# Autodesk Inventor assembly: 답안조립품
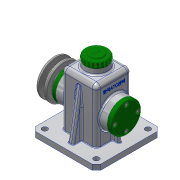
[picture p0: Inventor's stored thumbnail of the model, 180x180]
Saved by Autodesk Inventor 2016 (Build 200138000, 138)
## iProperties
Created: 2018-10
Part Number: 답안조립품
Material: 일반
Document SubType Name: Assembly
Designer: user
Author: user
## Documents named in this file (14)
- C:\Users\user\Desktop\481016V1009\답안조립품.iam
- C:\Users\user\Desktop\481016V1009\본체.ipt
- C:\Users\user\Desktop\481016V1009\뒤커버.ipt
- C:\Users\user\Desktop\481016V1009\앞커버.ipt
- C:\Users\user\Desktop\481016V1009\베어링 15 x 35 x 11.ipt
- C:\Users\user\Desktop\481016V1009\축.ipt
- C:\Users\user\Desktop\481016V1009\멈춤링 15 x 1.ipt
- C:\Users\user\Desktop\481016V1009\키 5 x 5 x 14.ipt
- C:\Users\user\Desktop\481016V1009\오일실 15 25 7.ipt
- C:\Users\user\Desktop\481016V1009\V-벨트풀리.ipt
- C:\Users\user\Desktop\481016V1009\볼트 M6 x 12.ipt
- C:\Users\user\Desktop\481016V1009\와셔.ipt
- C:\Users\user\Desktop\481016V1009\상부캡.ipt
- C:\Users\user\Desktop\481016V1009\볼트 M4 x 10.ipt
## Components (1 placed, 1 different names)
1. V-벨트풀리:1 — 각도:1
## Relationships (1: Angle 1)
- 각도:1 [Angle]: V-벨트풀리:1
